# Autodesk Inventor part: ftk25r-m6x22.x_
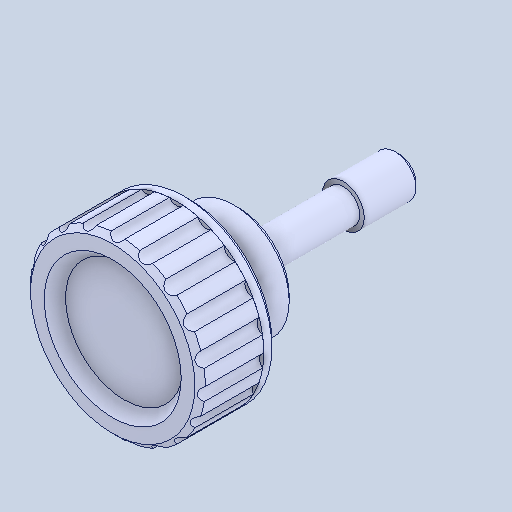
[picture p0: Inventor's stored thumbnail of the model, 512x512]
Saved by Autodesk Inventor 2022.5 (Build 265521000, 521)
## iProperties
Created: 2024-06
Part Number: ftk25r-m6x22.x_
Material: 一般
Document SubType Name: Modeling
Designer: ImaoCorp
Density: 1 g/cm^3
Appearance: 既定
Author: ImaoCorp
Sending System: SOLIDWORKS 2022-2022290
MC: AMD64
MC_MODEL: Intel64 Family 6 Model 60 Stepping 3, GenuineIntel
OS: Windows_NT
FRU: Parasolid Version 33.1, build 260,  4-25-2022
FORMAT: text
GUISE: transmit
KEY: FILEftk25r-m6x22.x_t
DATE: Fri Jun 28 15:19:33 2024
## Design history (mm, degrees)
feature "Base1"
node "ソリッド1"
